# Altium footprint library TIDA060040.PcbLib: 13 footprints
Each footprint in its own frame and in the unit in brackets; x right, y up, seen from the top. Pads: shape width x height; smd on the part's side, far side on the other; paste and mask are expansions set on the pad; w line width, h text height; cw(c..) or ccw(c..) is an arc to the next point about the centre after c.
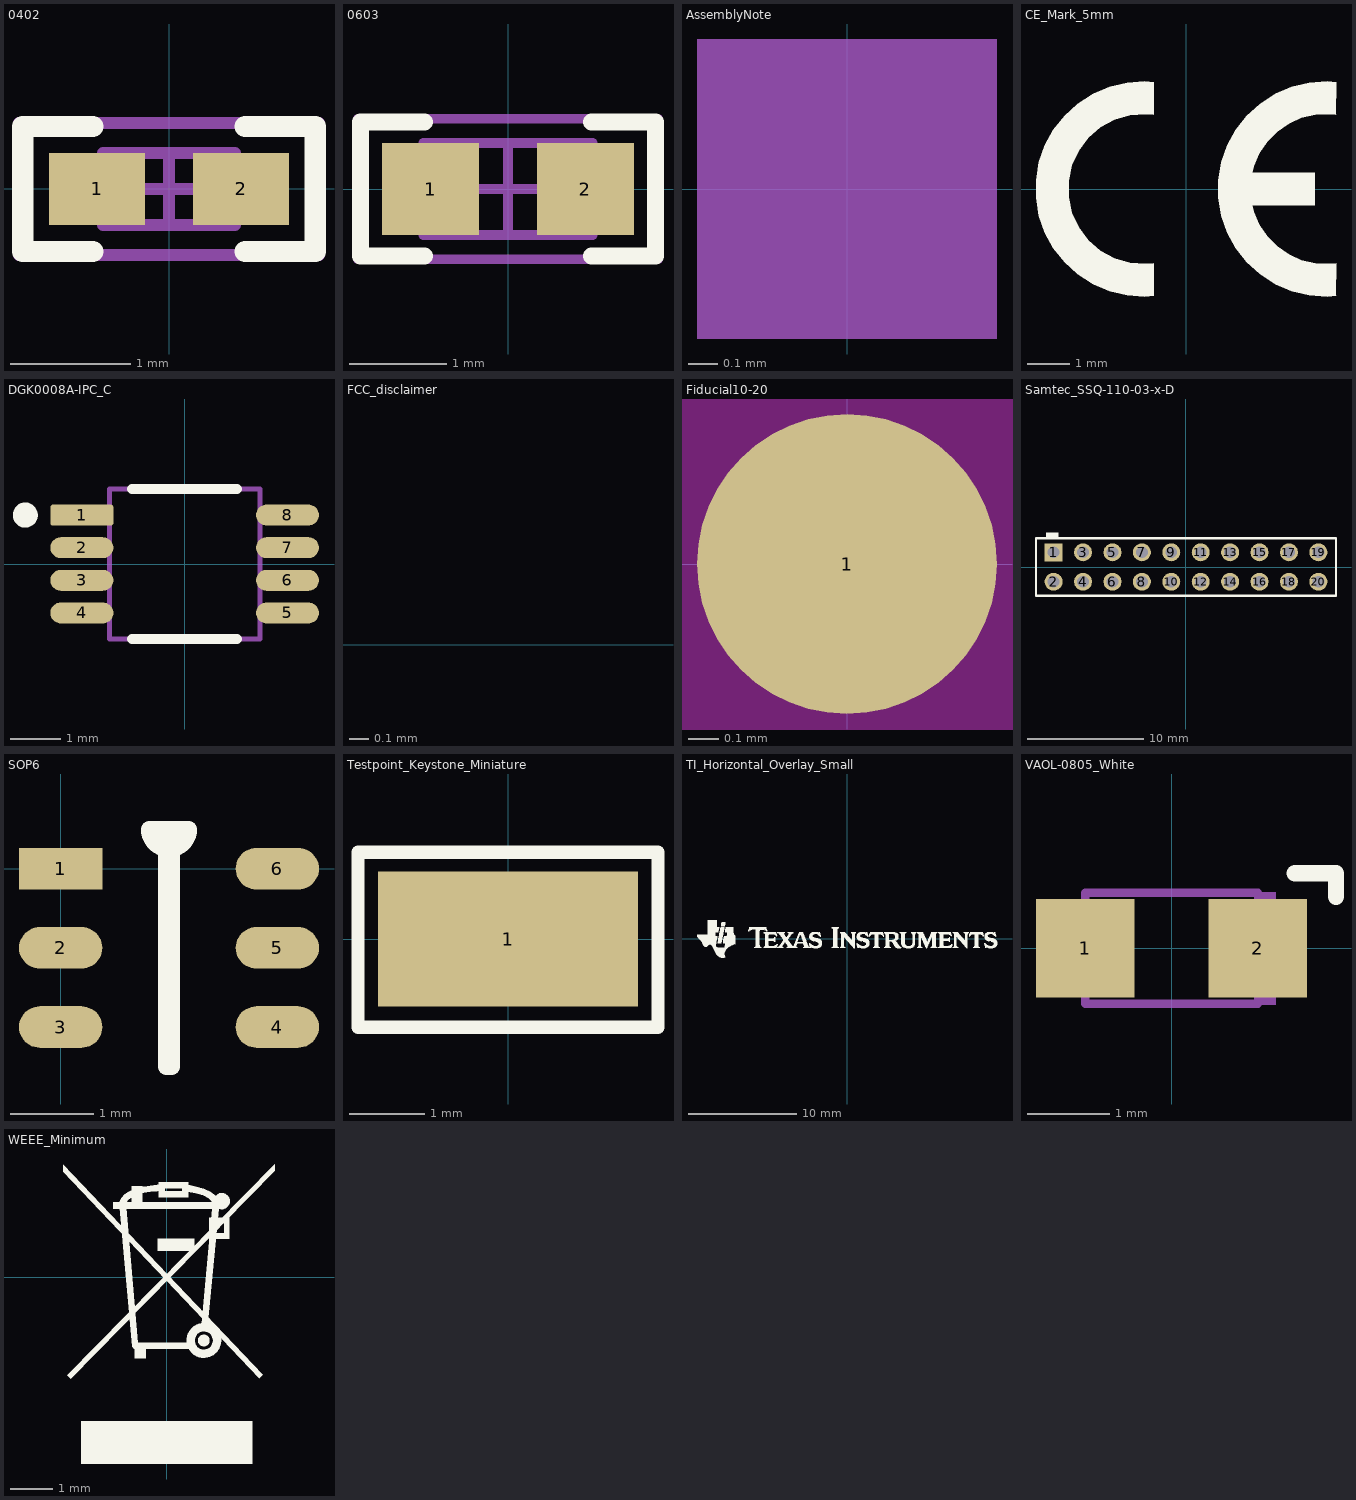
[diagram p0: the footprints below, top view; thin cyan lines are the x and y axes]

## 0402 [mm] "0402 from SM-752 data"
height 0.6
pads (2):
  rect 0.8x0.6 smd: 1(-0.6,0) 2(0.6,0)
Top Overlay:
  lines w0.178: -0.635,-0.521 -1.219,-0.521 -1.219,0.521 -0.635,0.521 ; 0.635,-0.521 1.219,-0.521 1.219,0.521 0.635,0.521
Mechanical 5:
  lines w0.1: -1.25,-0.55 -1.25,0.55 1.25,0.55 1.25,-0.55 -1.25,-0.55
  text ".Designator" at -1.117,-0.305 h0.61
Mechanical 13:
  lines w0.1: -0.35,-0.3 -0.35,0.3 ; 0.35,-0.3 0.35,0.3 ; -0.55,-0.3 0.55,-0.3 0.55,0.3 -0.55,0.3 -0.55,-0.3
Mechanical 15:
  lines w0.1: -0.3,0 0.3,0 ; 0,-0.3 0,0.3 ; -1.25,-0.55 1.25,-0.55 1.25,0.55 -1.25,0.55 -1.25,-0.55
3D body: height 0.6, standoff 0, extent 0.351,-0.299 0.549,0.299
3D body: height 0.6, standoff 0, extent -0.349,-0.299 0.349,0.299
3D body: height 0.6, standoff 0, extent -0.549,-0.299 -0.351,0.299

## 0603 [mm] "0603 from SM-752 data"
height 1
pads (2):
  rect 1x0.95 smd: 1(-0.8,0) 2(0.8,0)
Top Overlay:
  lines w0.178: -0.864,-0.691 -1.524,-0.691 -1.524,0.693 -0.864,0.693 ; 0.864,-0.691 1.524,-0.691 1.524,0.693 0.864,0.693
Mechanical 5:
  lines w0.1: -1.55,-0.725 -1.55,0.725 1.55,0.725 1.55,-0.725 -1.55,-0.725
  text ".Designator" at -1.397,-0.381 h0.76
Mechanical 13:
  lines w0.1: -0.55,-0.475 -0.55,0.475 ; 0.55,-0.475 0.55,0.475 ; -0.875,-0.475 0.875,-0.475 0.875,0.475 -0.875,0.475 -0.875,-0.475
Mechanical 15:
  lines w0.1: -0.475,0 0.475,0 ; 0,-0.475 0,0.475 ; -1.55,-0.725 1.55,-0.725 1.55,0.725 -1.55,0.725 -1.55,-0.725
3D body: height 1, standoff 0, extent -0.874,-0.474 -0.551,0.474
3D body: height 1, standoff 0, extent -0.549,-0.474 0.549,0.474
3D body: height 1, standoff 0, extent 0.551,-0.474 0.874,0.474

## AssemblyNote [mm] "Assembly Note"
Mechanical 5:
  rectangle: -0.508,-0.508 0.508,0.508
  text ".Comment" at 1.143,-0.508 h1.02
  text ".Designator" at -4.191,-0.508 h1.02

## CE_Mark_5mm [mm] "Minimum text height for CE Mark"
Top Overlay:
  region: 3.5,-1.732 3.337,-1.748 3.01,-1.733 2.691,-1.658 2.392,-1.525 2.123,-1.339 1.894,-1.106 1.712,-0.834 1.583,-0.533 1.541,-0.375 3,-0.375 3,0.375 1.541,0.375 1.583,0.533 1.712,0.834 1.894,1.106 2.123,1.339 2.392,1.525 2.691,1.658 3.01,1.733 3.337,1.748 3.5,1.732 3.5,2.487 3.292,2.508 2.874,2.48 2.467,2.383 2.081,2.22 1.728,1.994 1.418,1.714 1.158,1.385 0.957,1.018 0.82,0.622 0.75,0.209 0.75,-0.209 0.82,-0.622 0.957,-1.018 1.158,-1.385 1.418,-1.714 1.728,-1.994 2.081,-2.22 2.467,-2.383 2.874,-2.48 3.292,-2.508 3.5,-2.487
  region: -0.75,-2.487 -0.958,-2.508 -1.376,-2.48 -1.783,-2.383 -2.169,-2.22 -2.522,-1.994 -2.832,-1.714 -3.092,-1.385 -3.293,-1.018 -3.43,-0.622 -3.5,-0.209 -3.5,0.209 -3.43,0.622 -3.293,1.018 -3.092,1.385 -2.832,1.714 -2.522,1.994 -2.169,2.22 -1.783,2.383 -1.376,2.48 -0.958,2.508 -0.75,2.487 -0.75,1.732 -0.937,1.749 -1.31,1.722 -1.669,1.617 -1.998,1.438 -2.281,1.193 -2.505,0.893 -2.66,0.553 -2.74,0.187 -2.74,-0.187 -2.66,-0.553 -2.505,-0.893 -2.281,-1.193 -1.998,-1.438 -1.669,-1.617 -1.31,-1.722 -0.937,-1.749 -0.75,-1.732

## DGK0008A-IPC_C [mm]
pads (8):
  rrect24% 1.257x0.418 smd paste+0 mask+0: 1(-2.051,0.975)
  rrect100% 1.257x0.418 smd paste+0 mask+0: 2(-2.051,0.325) 3(-2.051,-0.325) 4(-2.051,-0.975) 5(2.051,-0.975) 6(2.051,-0.325) 7(2.051,0.325) 8(2.051,0.975)
Top Overlay:
  circle w0.25: c-3.179,0.975 r0.125
  lines w0.2: -1.048,-1.5 1.048,-1.5 ; -1.048,1.5 1.048,1.5
Mechanical 5:
  lines w0.1: -1.5,-1.5 1.5,-1.5 1.5,1.5 -1.5,1.5 -1.5,-1.5
  text ".Designator" at 0,0 h0.5
3D body "IC_TMAG5170A1QDGKR_VSSOP8.STEP": height 0.25, standoff 0, extent -2.779,-1.6 2.779,1.6

## FCC_disclaimer [mm]
Top Overlay:
  text "For evaluation only; not FCC approved for resale." at -15.928,-0.353 h1.52

## Fiducial10-20 [mm]
pads (1):
  round 1 smd mask+0.5: 1(0,0)
Top Layer keep-out:
  circle w1.178: c0,0 r0.5

## Samtec_SSQ-110-03-x-D [mm] "Receptacle, 2.54mm, 10x2, TH"
height 8.64
pads (20):
  rect 1.55x1.55 hole 1.02: 1(-11.43,1.27)
  round 1.55 hole 1.02: 2(-11.43,-1.27) 3(-8.89,1.27) 4(-8.89,-1.27) 5(-6.35,1.27) 6(-6.35,-1.27) 7(-3.81,1.27) 8(-3.81,-1.27) 9(-1.27,1.27) 10(-1.27,-1.27) 11(1.27,1.27) 12(1.27,-1.27) 13(3.81,1.27) 14(3.81,-1.27) 15(6.35,1.27) 16(6.35,-1.27) 17(8.89,1.27) 18(8.89,-1.27) 19(11.43,1.27) 20(11.43,-1.27)
Top Overlay:
  rectangle: -12.1,2.5 -11,3
  lines w0.2: -12.954,-2.476 -12.954,2.477 12.954,2.477 12.954,-2.476 -12.954,-2.476
Mechanical 5:
  lines w0.1: -12.954,-2.476 -12.954,2.477 12.954,2.477 12.954,-2.476 -12.954,-2.476
  text ".Designator" at -1.524,-0.508 h1.02
3D body "SSQ-110-03-T-D.stp": height 8.51, standoff -10.01, extent -12.954,-2.476 12.954,2.477

## SOP6 [mm]
pads (6):
  rect 1x0.5 smd: 1(0,0)
  oval 1x0.5 smd: 2(0,-0.95) 3(0,-1.9) 4(2.6,-1.9) 5(2.6,-0.95) 6(2.6,0)
Top Overlay:
  lines w0.2: 1.062,0.475 ccw(c1.3,0.475) 1.538,0.475 1.265,0.475 1.265,-2.375 1.335,-2.375 1.335,0.475 1.062,0.475

## Testpoint_Keystone_Miniature [mil] "Miniature SMT test point"
height 90.55
pads (1):
  rect 135x70 smd: 1(0,0)
Top Overlay:
  lines w7: -78,-46 78,-46 78,45 5,45 -65,45 -78,45 -78,-38 -78,-46
Mechanical 5:
  lines w5: -78,-46 -78,-38 -78,45 -65,45 5,45 78,45 78,-46 -78,-46
  text ".Designator" at -60,-15 h40
3D body "keystone_5015.stp": height 60.6, standoff 0.6, extent -52.5,-20 52.5,20

## TI_Horizontal_Overlay_Small [mm]
Top Overlay:
  drawing of 18 lines, arcs and shapes, not listed

## VAOL-0805_White [mm] "Visual Communications"
height 1.1
pads (2):
  rect 1.2x1.2 smd: 1(-1.05,0) 2(1.05,0)
Top Overlay:
  lines w0.2: 1.5,0.914 2,0.914 2,0.625
Mechanical 5:
  rectangle: 1.054,-0.688 1.27,0.686
  lines w0.1: -1.05,-0.675 1.05,-0.675 1.05,0.675 -1.05,0.675 -1.05,-0.675
  text ".Designator" at -0.94,-0.178 h0.51
3D body: height 1.1, standoff 0.5, extent -0.61,-0.675 0.61,0.675
3D body: height 0.5, standoff 0, extent -1.05,-0.675 1.05,0.675

## WEEE_Minimum [mm] "WEEElie bin"
Top Overlay:
  drawing of 23 lines, arcs and shapes, not listed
